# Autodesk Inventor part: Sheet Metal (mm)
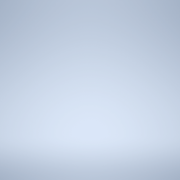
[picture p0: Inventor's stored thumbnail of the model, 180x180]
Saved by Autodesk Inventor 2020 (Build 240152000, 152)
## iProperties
Created: 2019-02
Part Number: Sheet Metal (mm)
Material: Ogólny
Document SubType Name: Konstrukcja blachowa
Density: 1 g/cm^3
Sheet Metal Rule: Domyślny_mm
Appearance: Domyślna
Designer: F.Stasiak
Manager: www.cadconsulting.pl
Company: Fabian Stasiak CAD Consulting
Subject: Zbiór ćwiczeń. Autodesk Inventor 2020. Kurs podstawowy
Author: F.Stasiak
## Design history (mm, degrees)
other parameters: "Grubość" = 0.5 (derived), "WspółczynnikK" = 4.4, "PromieńGięcia" = 0.5 (= Grubość), "SzerokośćGięciaPodcięcia" = 0.5 (= Grubość), "GłębokośćGięciaPodcięcia" = 0.25 (= 0.5 x Grubość), "RozmiarPodcięciaNarożnika" = 2 (= 4 x Grubość), "OdstępPołączenia" = 0.01, "MinimalnaPozostałość" = 1 (= 2 x Grubość), "PromieńPrzejścia" = 0.5 (= PromieńGięcia), "Rozmiar_promienia_Jacobiego" = 0.5 (= PromieńGięcia), "Wielk_odstępu" = 0.5 (= Grubość)
